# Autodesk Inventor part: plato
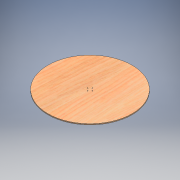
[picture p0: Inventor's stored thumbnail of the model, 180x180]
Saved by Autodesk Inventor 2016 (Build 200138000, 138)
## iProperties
Created: 2016-06
Part Number: plato
Material: Genérico
Document SubType Name: Modeling
Designer: adm
Density: 1 g/cm^3
Appearance: Valor por defecto
Author: adm
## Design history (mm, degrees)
sketch "Boceto1"
  geometry: C1 r 125 at (0, 0); C2 r 1 at (7, 0); C3 r 1 at (0, 7); C4 r 1 at (-7, 0); C5 r 1 at (0, -7); 3 further points
  constraints: 5 centre point, 3 coincident, 9 other
  dimensions: "d0" = 250 diameter of C1; "d3" = 7 distance of point (7, 0) point (0, 0); "d4" = 2 diameter of C2; "d7" = 360 deg dimension on point (0, 0) C2.centre (derived)
extrude "Extrusión1" new body sketch "Boceto1" distance "d9" = 3; taper "d10" = 0 deg
node "Sólido1"
